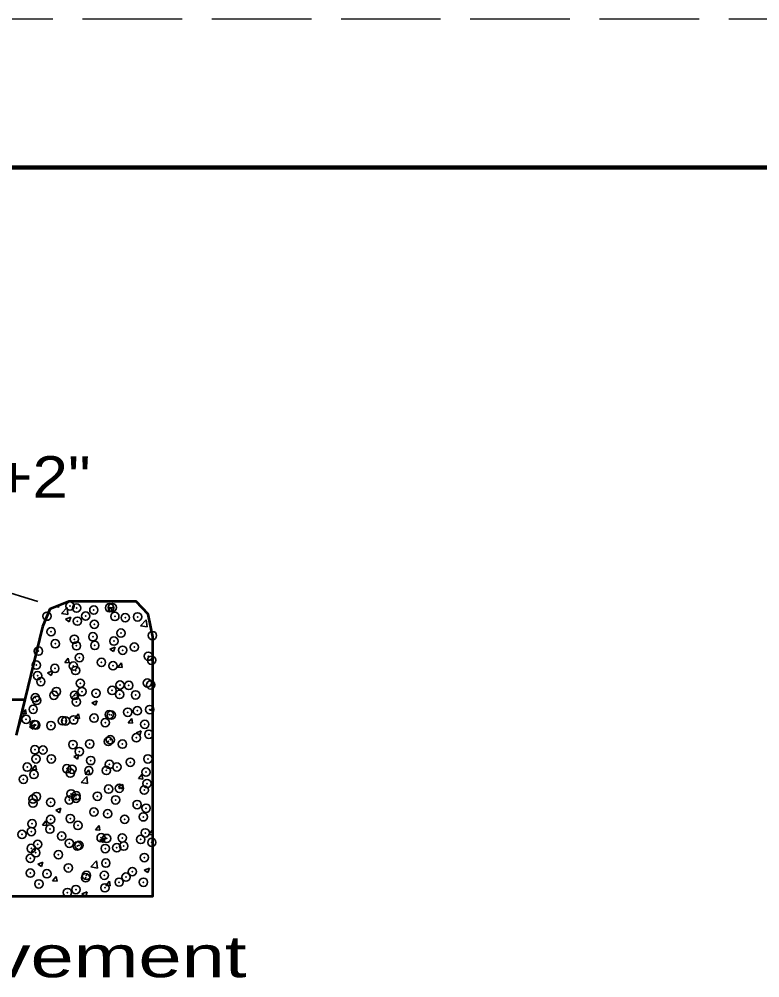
# Model space of a CAD drawing. Extents: x 14 to 49.3, y 28 to 50.
# Drawn here: x 29.007 to 31.505, y 46.81 to 50.044 of the extents above; entities that cross this region are included whole.
import ezdxf

# ---------------------------------------------------------------- set-up
doc = ezdxf.new("R2010")
doc.units = 0
doc.header["$LTSCALE"] = 0.056
doc.header["$PDMODE"] = 32
doc.header["$PDSIZE"] = 0.028
doc.linetypes.add('LONG_DASHED', pattern=[7.5, 6, -1.5])
for name, color, linetype, lineweight in [('1', 7, 'Continuous', 35), ('3', 7, 'Continuous', 13), ('6', 7, 'Continuous', 13)]:
    doc.layers.add(name, color=color, linetype=linetype, lineweight=lineweight)

msp = doc.modelspace()

# ---------------------------------------------------------------- linework, layer by layer
at = {"layer": '1', "linetype": 'LONG_DASHED', "lineweight": 25}
msp.add_line((49.17658, 50.04392), (13.97658, 50.04392), dxfattribs=at)
at = {"layer": '1', "lineweight": 158}
msp.add_line((49.09325, 49.54392), (16.59325, 49.54392), dxfattribs=at)
at = {"layer": '1'}
for p, q in [((29.07017, 48.08008), (28.31075, 48.31392)), ((29.12992, 48.06167), (29.14075, 48.06075)), ((29.14075, 48.06075), (29.13983, 48.06558)), ((29.14925, 48.039), (29.16875, 48.05933)), ((29.1715, 48.03558), (29.16875, 48.05925)), ((29.30508, 48.04633), (29.31717, 48.06075)), ((29.32008, 48.04508), (29.31717, 48.06075)), ((29.14925, 48.039), (29.1715, 48.03558)), ((29.16358, 48.01992), (29.18108, 48.02667)), ((29.16358, 48.01992), (29.176, 48.01158)), ((29.176, 48.01158), (29.18108, 48.02667)), ((29.30508, 48.04633), (29.32, 48.04508)), ((29.41608, 47.99758), (29.43558, 48.01792)), ((29.43833, 47.99417), (29.43558, 48.01792)), ((29.41608, 47.99758), (29.43833, 47.99417)), ((29.31275, 47.91933), (29.33025, 47.926)), ((29.32525, 47.91092), (29.33033, 47.926)), ((29.32525, 47.91092), (29.33033, 47.926)), ((29.16042, 47.874), (29.1725, 47.88833)), ((29.17542, 47.87267), (29.1725, 47.88833)), ((29.31275, 47.91933), (29.32525, 47.91092)), ((29.16042, 47.874), (29.17542, 47.87267)), ((29.33975, 47.85833), (29.35183, 47.87267)), ((29.33975, 47.85833), (29.35475, 47.857)), ((29.35475, 47.857), (29.35183, 47.87267)), ((29.10275, 47.83867), (29.12025, 47.84542)), ((29.10275, 47.83867), (29.11517, 47.83025)), ((29.11517, 47.83025), (29.12025, 47.84533)), ((29.18242, 47.75408), (29.20192, 47.77442)), ((29.20467, 47.75067), (29.20192, 47.77442)), ((29.18242, 47.75408), (29.20467, 47.75067)), ((29.25192, 47.738), (29.26942, 47.74475)), ((29.25192, 47.738), (29.26442, 47.72958)), ((29.26442, 47.72958), (29.2695, 47.74475)), ((29.01583, 47.70167), (29.02792, 47.716)), ((29.01583, 47.70167), (29.03075, 47.70033)), ((29.03075, 47.70033), (29.02792, 47.716)), ((29.19517, 47.68592), (29.20717, 47.70033)), ((29.21008, 47.68467), (29.20725, 47.70033)), ((29.44925, 47.71275), (29.45792, 47.72183)), ((29.44925, 47.71275), (29.45792, 47.71133)), ((29.04192, 47.65733), (29.05942, 47.66408)), ((29.05433, 47.649), (29.05942, 47.66408)), ((29.19517, 47.68592), (29.21008, 47.68467)), ((29.3745, 47.67025), (29.3865, 47.68467)), ((29.3745, 47.67025), (29.38942, 47.669)), ((29.38942, 47.66892), (29.3865, 47.68458)), ((29.04192, 47.65733), (29.05433, 47.649)), ((29.40117, 47.63733), (29.41867, 47.64408)), ((29.40117, 47.63733), (29.41358, 47.629)), ((29.41358, 47.62892), (29.41867, 47.64408)), ((29.19108, 47.55675), (29.20858, 47.56342)), ((29.19108, 47.55675), (29.20358, 47.54833)), ((29.20358, 47.54833), (29.20867, 47.56342)), ((29.0505, 47.51358), (29.06258, 47.528)), ((29.0505, 47.51358), (29.0655, 47.51225)), ((29.0655, 47.51225), (29.06258, 47.52792)), ((29.22983, 47.49792), (29.24192, 47.51225)), ((29.24483, 47.49658), (29.24192, 47.51225)), ((29.21558, 47.46917), (29.235, 47.4895)), ((29.21558, 47.46917), (29.23775, 47.46575)), ((29.22983, 47.49792), (29.24475, 47.49658)), ((29.23783, 47.46575), (29.235, 47.4895)), ((29.40917, 47.48225), (29.42117, 47.49658)), ((29.40917, 47.48225), (29.42408, 47.48092)), ((29.42408, 47.48092), (29.42125, 47.49658)), ((29.34033, 47.45608), (29.35783, 47.46275)), ((29.34033, 47.45608), (29.35275, 47.44767)), ((29.35283, 47.44767), (29.35783, 47.46275)), ((29.13025, 47.37542), (29.14775, 47.38217)), ((29.13025, 47.37542), (29.14275, 47.36708)), ((29.14275, 47.367), (29.14783, 47.38217)), ((29.08517, 47.32558), (29.09725, 47.33992)), ((29.10017, 47.32425), (29.09725, 47.33992)), ((29.08517, 47.32558), (29.10017, 47.32425)), ((29.2645, 47.30983), (29.27658, 47.32425)), ((29.2645, 47.30983), (29.2795, 47.30858)), ((29.2795, 47.30858), (29.27658, 47.32425)), ((29.44383, 47.29417), (29.45592, 47.3085)), ((29.45792, 47.2975), (29.45592, 47.3085)), ((29.2795, 47.27475), (29.297, 47.2815)), ((29.2795, 47.27475), (29.29192, 47.26642)), ((29.292, 47.26642), (29.297, 47.2815)), ((29.44383, 47.29417), (29.45792, 47.29292)), ((29.06942, 47.19417), (29.087, 47.20083)), ((29.06942, 47.19417), (29.08192, 47.18575)), ((29.08192, 47.18575), (29.087, 47.20083)), ((29.24867, 47.18425), (29.26817, 47.20458)), ((29.24867, 47.18425), (29.27092, 47.18083)), ((29.27092, 47.18083), (29.26817, 47.20458)), ((29.42875, 47.17408), (29.44625, 47.18083)), ((29.44117, 47.16575), (29.44625, 47.18083)), ((29.11992, 47.1375), (29.13192, 47.15183)), ((29.13483, 47.13617), (29.132, 47.15183)), ((29.42875, 47.17408), (29.44117, 47.16575)), ((29.11992, 47.1375), (29.13483, 47.13617)), ((29.29925, 47.12183), (29.31125, 47.13617)), ((29.29925, 47.12183), (29.31417, 47.1205)), ((29.31417, 47.1205), (29.31125, 47.13617)), ((29.21867, 47.0935), (29.23617, 47.10025)), ((29.21867, 47.0935), (29.2295, 47.08617)), ((29.2315, 47.08617), (29.23617, 47.10017))]:
    msp.add_line(p, q, dxfattribs=at)
at = {"layer": '1', "lineweight": 13}
msp.add_line((29.02792, 47.716), (28.99683, 47.62942), dxfattribs=at)
at = {"layer": '1', "lineweight": 53}
for points in [[(26.06008, 47.08617), (29.45792, 47.08617), (29.45792, 47.9605), (29.44175, 48.03692), (29.40133, 48.07933), (29.17475, 48.07933), (29.11008, 48.05392), (29.08583, 47.9945), (28.99683, 47.62942)], [(29.02583, 47.74833), (26.06825, 47.74833), (26.06825, 47.62942)]]:
    msp.add_lwpolyline(points, dxfattribs=at)
at = {"layer": '1'}
for p in [(29.17842, 48.06433), (29.20067, 48.05775), (29.25875, 48.051), (29.31192, 48.05867), (29.32133, 48.05925), (29.10092, 48.03025), (29.20333, 48.01342), (29.23117, 48.03075), (29.32967, 48.02942), (29.36458, 48.02508), (29.40633, 48.02792), (29.11475, 47.97783), (29.26058, 48.00283), (29.35025, 47.97308), (29.193, 47.95242), (29.25558, 47.96067), (29.32658, 47.94625), (29.45642, 47.965), (29.072, 47.91258), (29.12867, 47.93725), (29.20033, 47.93025), (29.26217, 47.93158), (29.35608, 47.91542), (29.39558, 47.92592), (29.21025, 47.89033), (29.2845, 47.8745), (29.44242, 47.89533), (29.45342, 47.88175), (29.06442, 47.86533), (29.12725, 47.85383), (29.18983, 47.86208), (29.19725, 47.847), (29.32358, 47.863), (29.06892, 47.82942), (29.08, 47.8095), (29.21342, 47.80383), (29.3205, 47.77975), (29.34692, 47.79825), (29.37667, 47.79667), (29.43925, 47.80492), (29.45033, 47.7985), (29.0615, 47.75517), (29.06592, 47.74617), (29.12408, 47.76342), (29.13275, 47.77592), (29.19425, 47.76375), (29.21875, 47.77592), (29.26617, 47.77025), (29.34575, 47.76625), (29.39958, 47.76467), (29.05417, 47.71617), (29.19992, 47.74117), (29.44733, 47.71533), (29.03025, 47.68242), (29.19125, 47.68058), (29.25983, 47.68633), (29.31083, 47.69808), (29.3175, 47.69658), (29.37342, 47.70633), (29.40567, 47.71133), (29.05833, 47.66483), (29.06283, 47.66292), (29.114, 47.66125), (29.153, 47.67733), (29.16375, 47.67675), (29.29717, 47.67117), (29.43067, 47.6655), (29.40233, 47.62017), (29.44433, 47.63208), (29.18817, 47.59733), (29.24508, 47.5995), (29.30767, 47.60775), (29.31442, 47.61333), (29.35533, 47.59883), (29.05983, 47.57975), (29.08725, 47.57867), (29.2095, 47.57375), (29.03425, 47.52108), (29.06375, 47.54875), (29.115, 47.549), (29.2485, 47.54342), (29.31142, 47.53008), (29.33658, 47.52158), (29.38192, 47.53775), (29.44125, 47.54883), (29.05675, 47.4965), (29.16775, 47.51542), (29.17933, 47.50092), (29.18517, 47.51408), (29.24192, 47.50908), (29.30117, 47.50983), (29.43467, 47.50417), (29.02142, 47.48008), (29.43825, 47.46567), (29.06533, 47.42192), (29.18208, 47.43092), (29.19917, 47.42458), (29.27083, 47.423), (29.30833, 47.44692), (29.345, 47.44967), (29.42875, 47.44375), (29.05342, 47.39958), (29.05375, 47.41325), (29.11358, 47.40225), (29.17617, 47.4105), (29.19875, 47.41633), (29.33217, 47.41067), (29.40492, 47.39475), (29.25908, 47.36975), (29.30533, 47.36367), (29.43517, 47.38242), (29.05067, 47.33008), (29.11333, 47.34467), (29.17908, 47.34767), (29.20508, 47.32442), (29.36292, 47.34517), (29.42558, 47.35342), (29.01658, 47.29417), (29.04783, 47.30367), (29.11042, 47.31192), (29.43217, 47.29917), (29.06933, 47.26058), (29.15008, 47.28858), (29.176, 47.26442), (29.2835, 47.28292), (29.30225, 47.28042), (29.35458, 47.28225), (29.417, 47.27725), (29.45442, 47.26725), (29.04767, 47.24683), (29.063, 47.23217), (29.20275, 47.255), (29.20875, 47.25725), (29.29717, 47.24658), (29.33625, 47.24933), (29.35975, 47.25483), (29.04458, 47.21333), (29.13933, 47.22575), (29.29925, 47.19725), (29.42908, 47.216), (29.04458, 47.16358), (29.173, 47.18125), (29.38867, 47.16867), (29.10033, 47.1615), (29.23142, 47.148), (29.23375, 47.15583), (29.294, 47.15617), (29.34425, 47.13308), (29.36725, 47.15017), (29.42608, 47.13275), (29.0735, 47.12717), (29.16992, 47.098), (29.19842, 47.10808), (29.29617, 47.114)]:
    msp.add_point(p, dxfattribs=at)
at = {"layer": '6', "lineweight": 25}
msp.add_line((29.12992, 48.06167), (29.13, 48.06167), dxfattribs=at)

# ---------------------------------------------------------------- texts
at = {"layer": '1', "width": 1.15}
msp.add_text('h+2"', height=0.14, dxfattribs=at).set_placement((28.80642, 48.42992))
at = {"layer": '3', "width": 1.4}
msp.add_text('Concrete Transition Pavement', height=0.14, dxfattribs=at).set_placement((26.23367, 46.81242))

doc.saveas('drawing.dxf')
